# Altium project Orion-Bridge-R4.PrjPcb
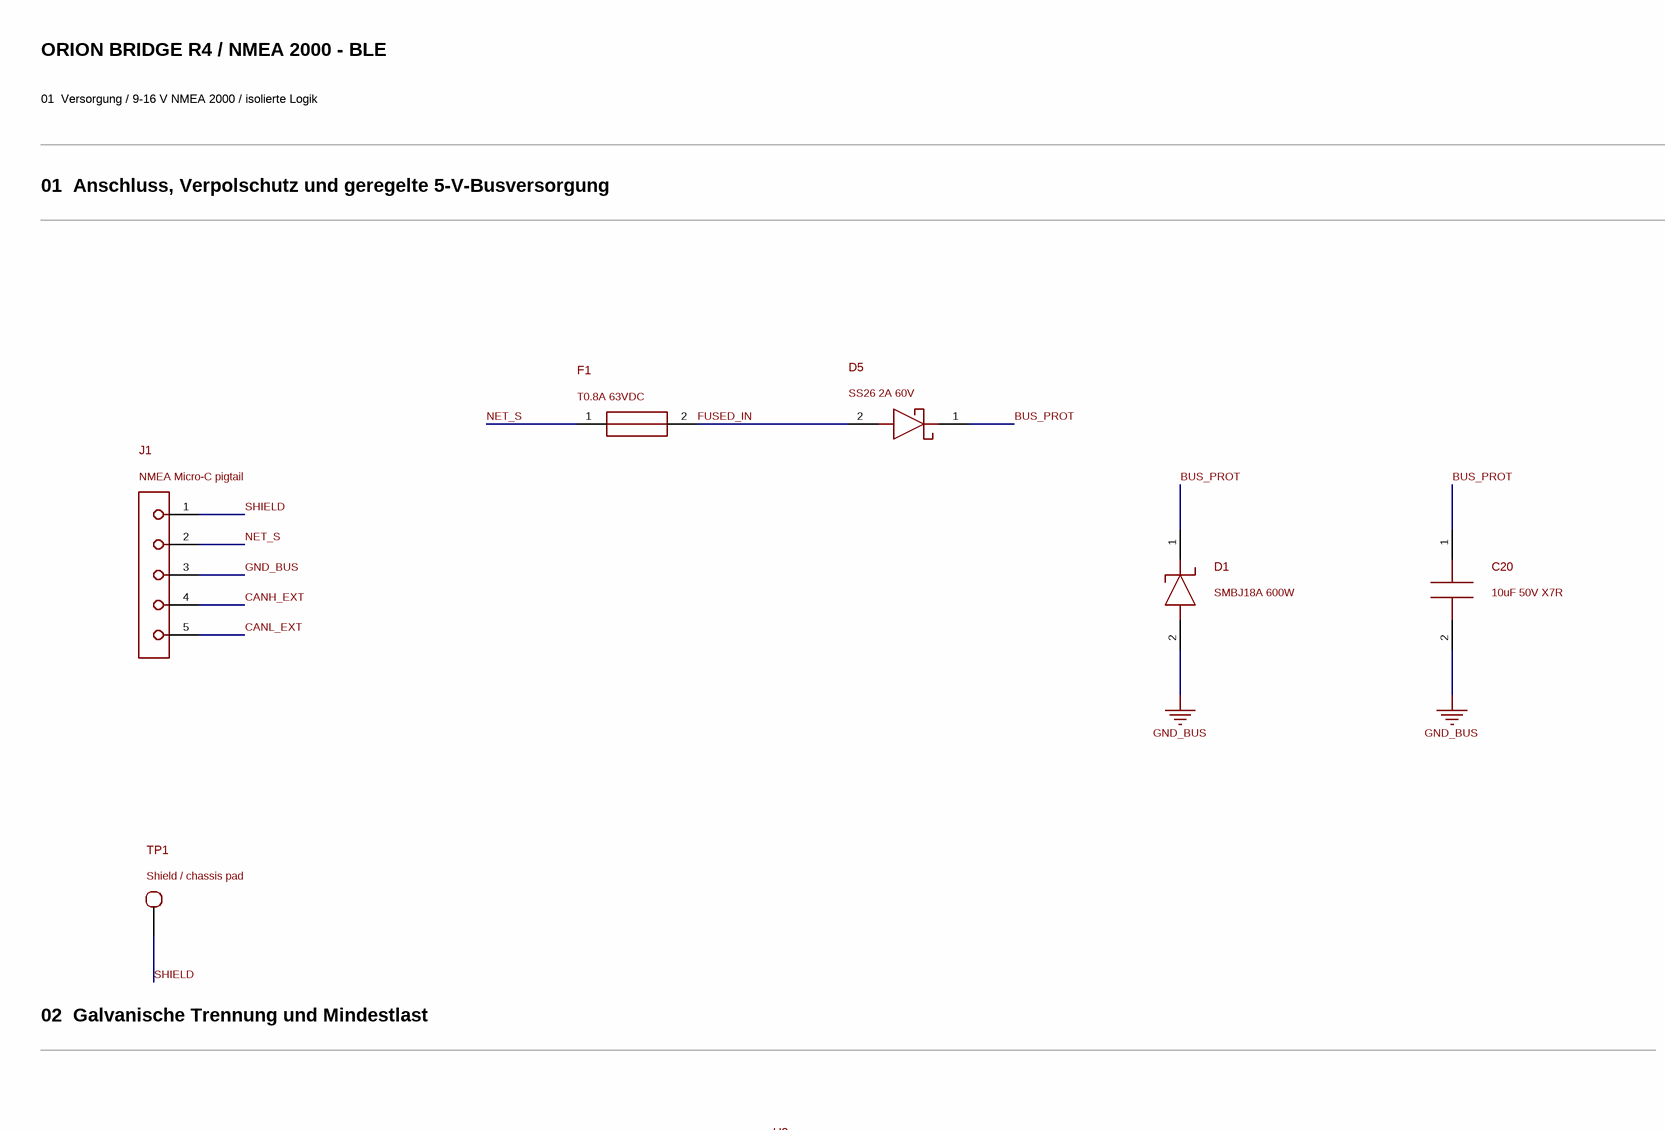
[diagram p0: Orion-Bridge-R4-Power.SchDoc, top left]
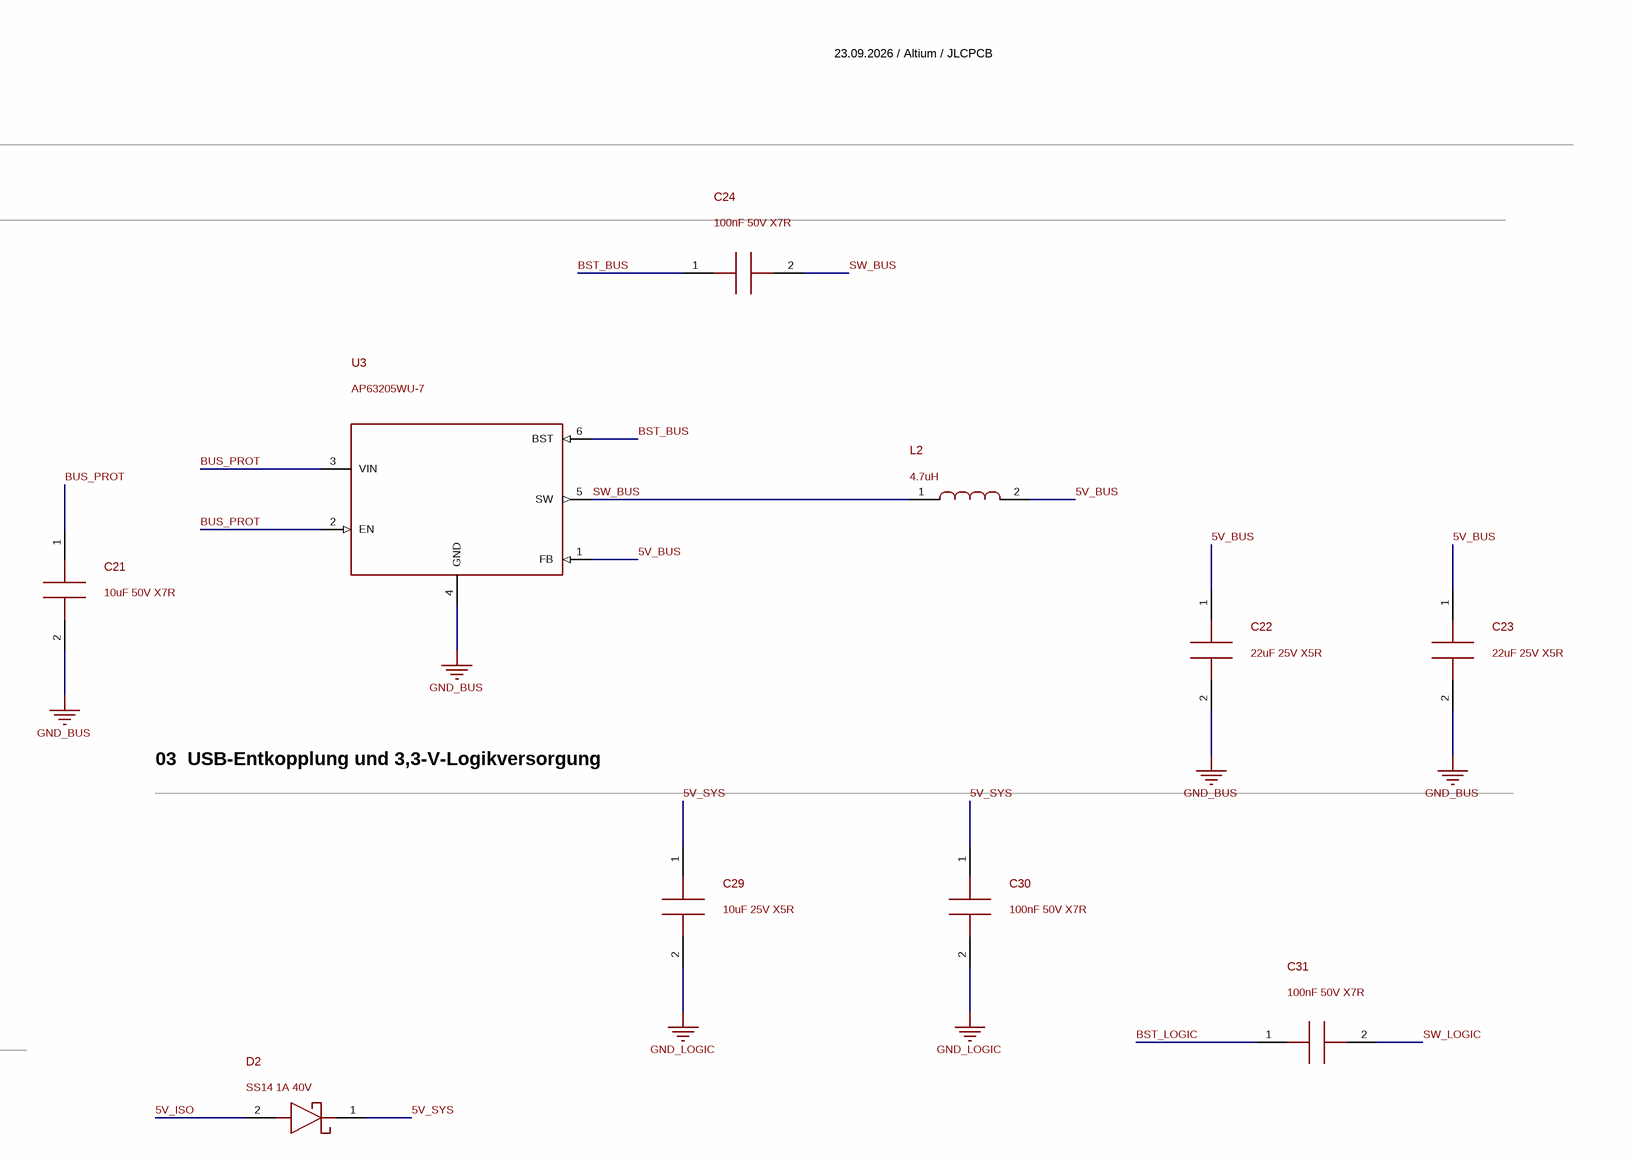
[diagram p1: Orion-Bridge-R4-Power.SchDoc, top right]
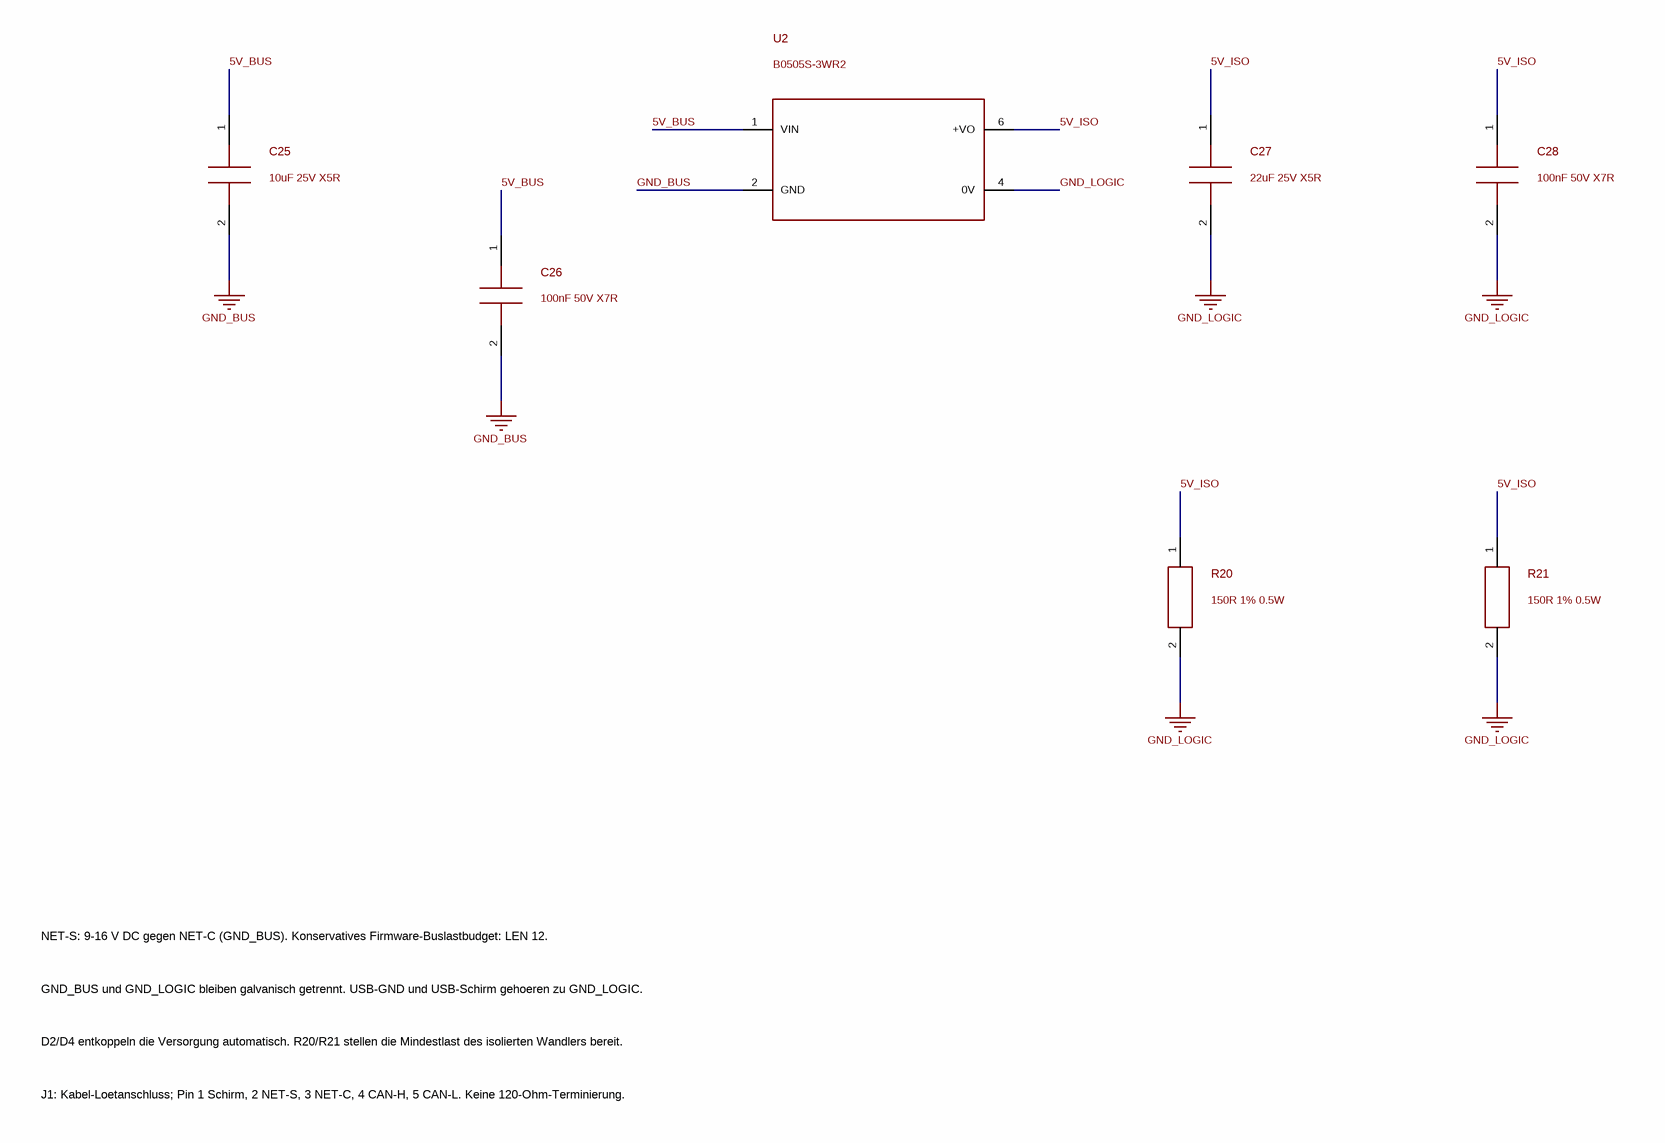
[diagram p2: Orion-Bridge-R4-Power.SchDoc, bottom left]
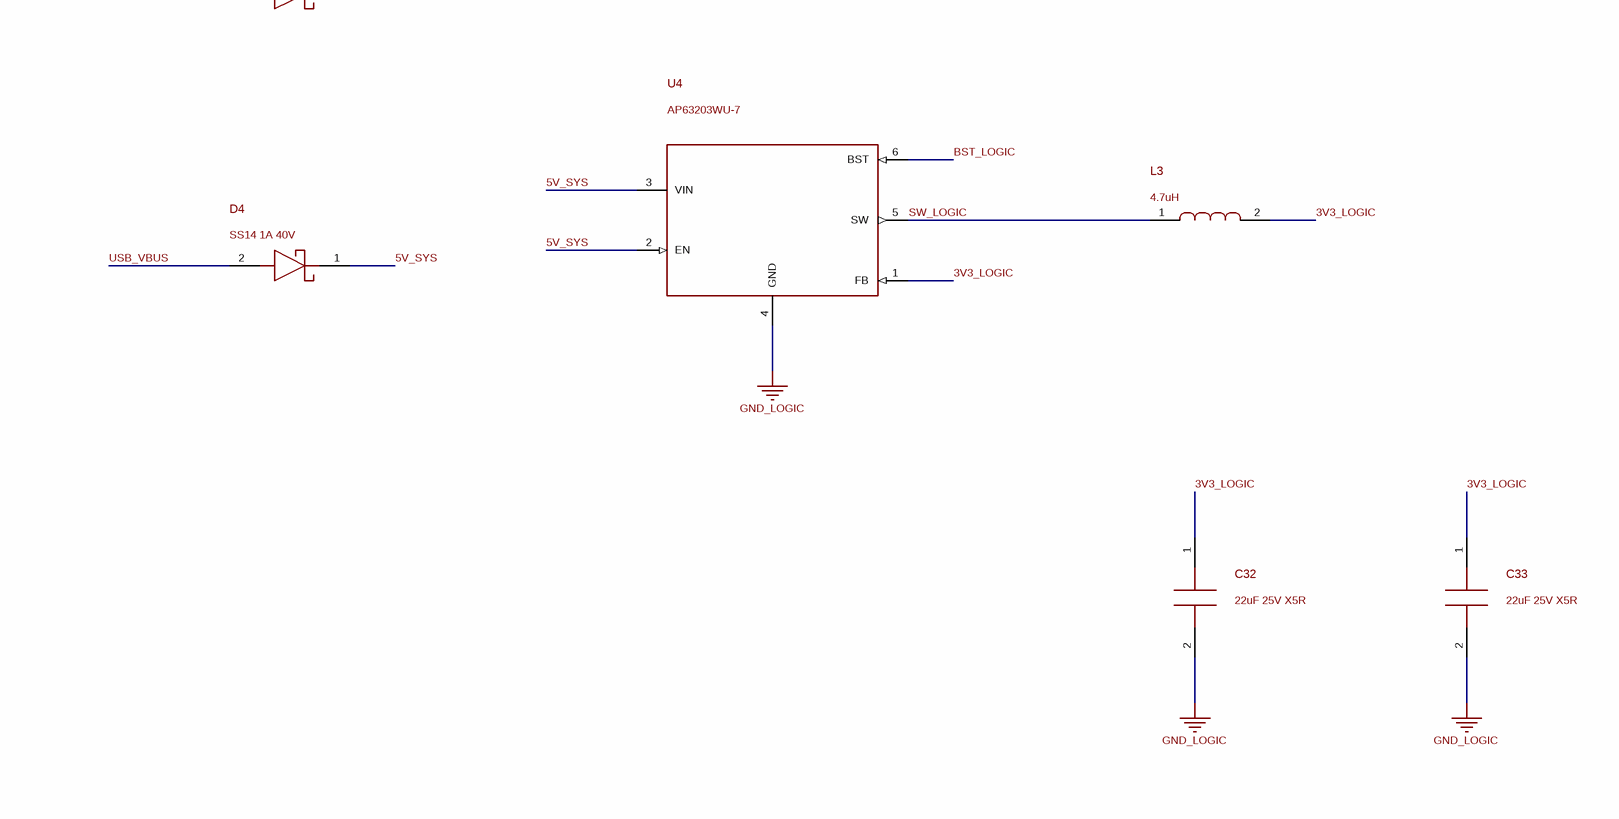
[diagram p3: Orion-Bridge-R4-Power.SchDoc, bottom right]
2 sheets, 52 parts. Net scope: global (net labels, ports and power ports of the same name join across sheets).
Board file: Orion-Bridge-R4.PcbDoc
Sheets:
  Orion-Bridge-R4-Power.SchDoc
  Orion-Bridge-R4-Logic.SchDoc

## Sheet Orion-Bridge-R4-Power.SchDoc
size A2

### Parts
C20  10uF 50V X7R  [C1210]
C21  10uF 50V X7R  [C1210]
C22  22uF 25V X5R  [C1206]
C23  22uF 25V X5R  [C1206]
C24  100nF 50V X7R  [C0603]
C25  10uF 25V X5R  [C0805]
C26  100nF 50V X7R  [C0603]
C27  22uF 25V X5R  [C1206]
C28  100nF 50V X7R  [C0603]
C29  10uF 25V X5R  [C0805]
C30  100nF 50V X7R  [C0603]
C31  100nF 50V X7R  [C0603]
C32  22uF 25V X5R  [C1206]
C33  22uF 25V X5R  [C1206]
D1  SMBJ18A 600W  [SMB]
D2  SS14 1A 40V  [SMA]
D4  SS14 1A 40V  [SMA]
D5  SS26 2A 60V  [SMA]
F1  T0.8A 63VDC  [BOURNS_SF1206S]
J1  NMEA Micro-C pigtail  [PIGTAIL_5_P3_D1P3]
L2  4.7uH  [SUNLORD_SWPA4030]
L3  4.7uH  [SUNLORD_SWPA4030]
R20  150R 1% 0.5W  [R1206]
R21  150R 1% 0.5W  [R1206]
TP1  Shield / chassis pad  [TESTPOINT_2MM]
U2  B0505S-3WR2  [EVISUN_B0505S_3WR2]
U3  AP63205WU-7  [TSOT26_DIODES]
U4  AP63203WU-7  [TSOT26_DIODES]

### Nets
GND_BUS: C20.2 C21.2 C22.2 C23.2 C25.2 C26.2 D1.2(A) J1.3(NET-C) U2.2(GND) U3.4(GND)
GND_LOGIC: C27.2 C28.2 C29.2 C30.2 C32.2 C33.2 R20.2 R21.2 U2.4(0V) U4.4(GND)
3V3_LOGIC: C32.1 C33.1 L3.2 U4.1(FB)
5V_BUS: C22.1 C23.1 C25.1 C26.1 L2.2 U2.1(VIN) U3.1(FB)
5V_ISO: C27.1 C28.1 D2.2(A) R20.1 R21.1 U2.6(+VO)
5V_SYS: C29.1 C30.1 D2.1(K) D4.1(K) U4.2(EN) U4.3(VIN)
BST_BUS: C24.1 U3.6(BST)
BST_LOGIC: C31.1 U4.6(BST)
BUS_PROT: C20.1 C21.1 D1.1(K) D5.1(K) U3.2(EN) U3.3(VIN)
CANH_EXT: J1.4(CAN-H)
CANL_EXT: J1.5(CAN-L)
FUSED_IN: D5.2(A) F1.2
NET_S: F1.1 J1.2(NET-S)
SHIELD: J1.1(SHIELD) TP1.1(SHIELD)
SW_BUS: C24.2 L2.1 U3.5(SW)
SW_LOGIC: C31.2 L3.1 U4.5(SW)
USB_VBUS: D4.2(A)

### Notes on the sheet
- ORION BRIDGE R4 / NMEA 2000 - BLE
- 23.09.2026 / Altium / JLCPCB
- 01  Versorgung / 9-16 V NMEA 2000 / isolierte Logik
- 01  Anschluss, Verpolschutz und geregelte 5-V-Busversorgung
- 03  USB-Entkopplung und 3,3-V-Logikversorgung
- 02  Galvanische Trennung und Mindestlast
- NET-S: 9-16 V DC gegen NET-C (GND_BUS). Konservatives Firmware-Buslastbudget: LEN 12.
- GND_BUS und GND_LOGIC bleiben galvanisch getrennt. USB-GND und USB-Schirm gehoeren zu GND_LOGIC.
- D2/D4 entkoppeln die Versorgung automatisch. R20/R21 stellen die Mindestlast des isolierten Wandlers bereit.
- J1: Kabel-Loetanschluss; Pin 1 Schirm, 2 NET-S, 3 NET-C, 4 CAN-H, 5 CAN-L. Keine 120-Ohm-Terminierung.

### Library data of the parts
C20 = R4_C20_10uF: Manufacturer: Samsung Electro-Mechanics; MPN: CL32B106KBJNNNE; ReviewStatus: R4 reviewed package; see source and assembly audit
C21 = R4_C21_10uF: Manufacturer: Samsung Electro-Mechanics; MPN: CL32B106KBJNNNE; ReviewStatus: R4 reviewed package; see source and assembly audit
C22 = R4_C22_22uF: Manufacturer: Samsung Electro-Mechanics; MPN: CL31A226KAHNNNE; ReviewStatus: R4 reviewed package; see source and assembly audit
C23 = R4_C23_22uF: Manufacturer: Samsung Electro-Mechanics; MPN: CL31A226KAHNNNE; ReviewStatus: R4 reviewed package; see source and assembly audit
C24 = R4_C24_100nF: Manufacturer: YAGEO; MPN: CC0603KRX7R9BB104; ReviewStatus: R4 reviewed package; see source and assembly audit
C25 = R4_C25_10uF: Manufacturer: Samsung Electro-Mechanics; MPN: CL21A106KAYNNNE; ReviewStatus: R4 reviewed package; see source and assembly audit
C26 = R4_C26_100nF: Manufacturer: YAGEO; MPN: CC0603KRX7R9BB104; ReviewStatus: R4 reviewed package; see source and assembly audit
C27 = R4_C27_22uF: Manufacturer: Samsung Electro-Mechanics; MPN: CL31A226KAHNNNE; ReviewStatus: R4 reviewed package; see source and assembly audit
C28 = R4_C28_100nF: Manufacturer: YAGEO; MPN: CC0603KRX7R9BB104; ReviewStatus: R4 reviewed package; see source and assembly audit
C29 = R4_C29_10uF: Manufacturer: Samsung Electro-Mechanics; MPN: CL21A106KAYNNNE; ReviewStatus: R4 reviewed package; see source and assembly audit
C30 = R4_C30_100nF: Manufacturer: YAGEO; MPN: CC0603KRX7R9BB104; ReviewStatus: R4 reviewed package; see source and assembly audit
C31 = R4_C31_100nF: Manufacturer: YAGEO; MPN: CC0603KRX7R9BB104; ReviewStatus: R4 reviewed package; see source and assembly audit
C32 = R4_C32_22uF: Manufacturer: Samsung Electro-Mechanics; MPN: CL31A226KAHNNNE; ReviewStatus: R4 reviewed package; see source and assembly audit
C33 = R4_C33_22uF: Manufacturer: Samsung Electro-Mechanics; MPN: CL31A226KAHNNNE; ReviewStatus: R4 reviewed package; see source and assembly audit
D1 = R4_D1_SMBJ18A: Manufacturer: BORN; ReviewStatus: R4 reviewed package; see source and assembly audit
D2 = R4_D2_SS14: Manufacturer: MDD(Microdiode Semiconductor); ReviewStatus: R4 reviewed package; see source and assembly audit
D4 = R4_D4_SS14: Manufacturer: MDD(Microdiode Semiconductor); ReviewStatus: R4 reviewed package; see source and assembly audit
D5 = R4_D5_SS26: Manufacturer: MDD(Microdiode Semiconductor); ReviewStatus: R4 reviewed package; see source and assembly audit
F1 = R4_F1_T0.8A: 0.8 A slow-blow SMD ceramic fuse, 63 VDC, 50 A interrupt rating; Manufacturer: BOURNS; MPN: SF-1206S080-2; ReviewStatus: R4 reviewed package; see source and assembly audit
J1 = R4_J1_NMEA: Five direct wire-solder pads for a separately selected Micro-C cable; this is a PCB interface, not an invented connector MPN or face view; ReviewStatus: R4 reviewed package; see source and assembly audit
L2 = R4_L2_4.7uH: Manufacturer: Sunlord; MPN: SWPA4030S4R7MT; ReviewStatus: R4 reviewed package; see source and assembly audit
L3 = R4_L3_4.7uH: Manufacturer: Sunlord; MPN: SWPA4030S4R7MT; ReviewStatus: R4 reviewed package; see source and assembly audit
R20 = R4_R20_150R: Manufacturer: SEI(Stackpole Elec); MPN: RNCP1206FTD150R; ReviewStatus: R4 reviewed package; see source and assembly audit
R21 = R4_R21_150R: Manufacturer: SEI(Stackpole Elec); MPN: RNCP1206FTD150R; ReviewStatus: R4 reviewed package; see source and assembly audit
TP1 = R4_TP1_Shield: Shield / chassis pad - generic specification; manufacturer/MPN not selected; ReviewStatus: R4 reviewed package; see source and assembly audit
U2 = R4_U2_B0505S_3WR2: Manufacturer: EVISUN; ReviewStatus: R4 reviewed package; see source and assembly audit
U3 = R4_U3_AP63205WU_7: Manufacturer: Diodes Incorporated; ReviewStatus: R4 reviewed package; see source and assembly audit
U4 = R4_U4_AP63203WU_7: Manufacturer: Diodes Incorporated; ReviewStatus: R4 reviewed package; see source and assembly audit

## Sheet Orion-Bridge-R4-Logic.SchDoc
size A2
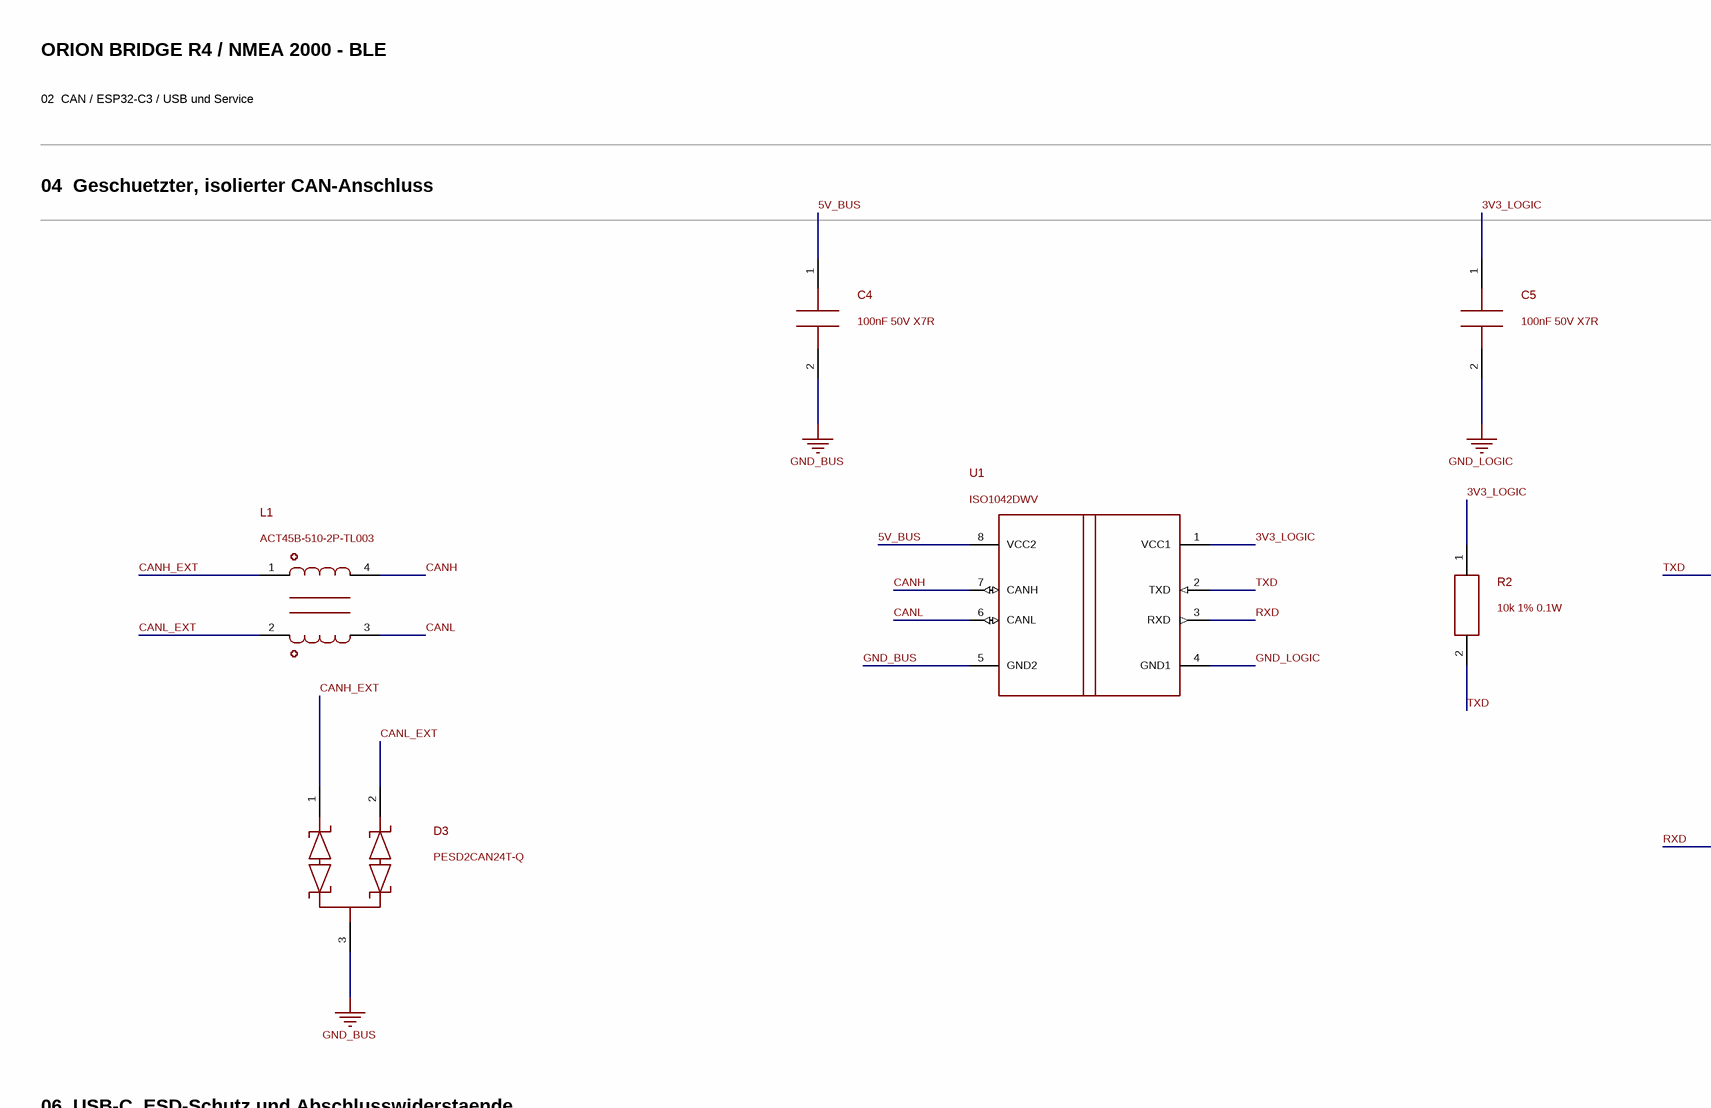
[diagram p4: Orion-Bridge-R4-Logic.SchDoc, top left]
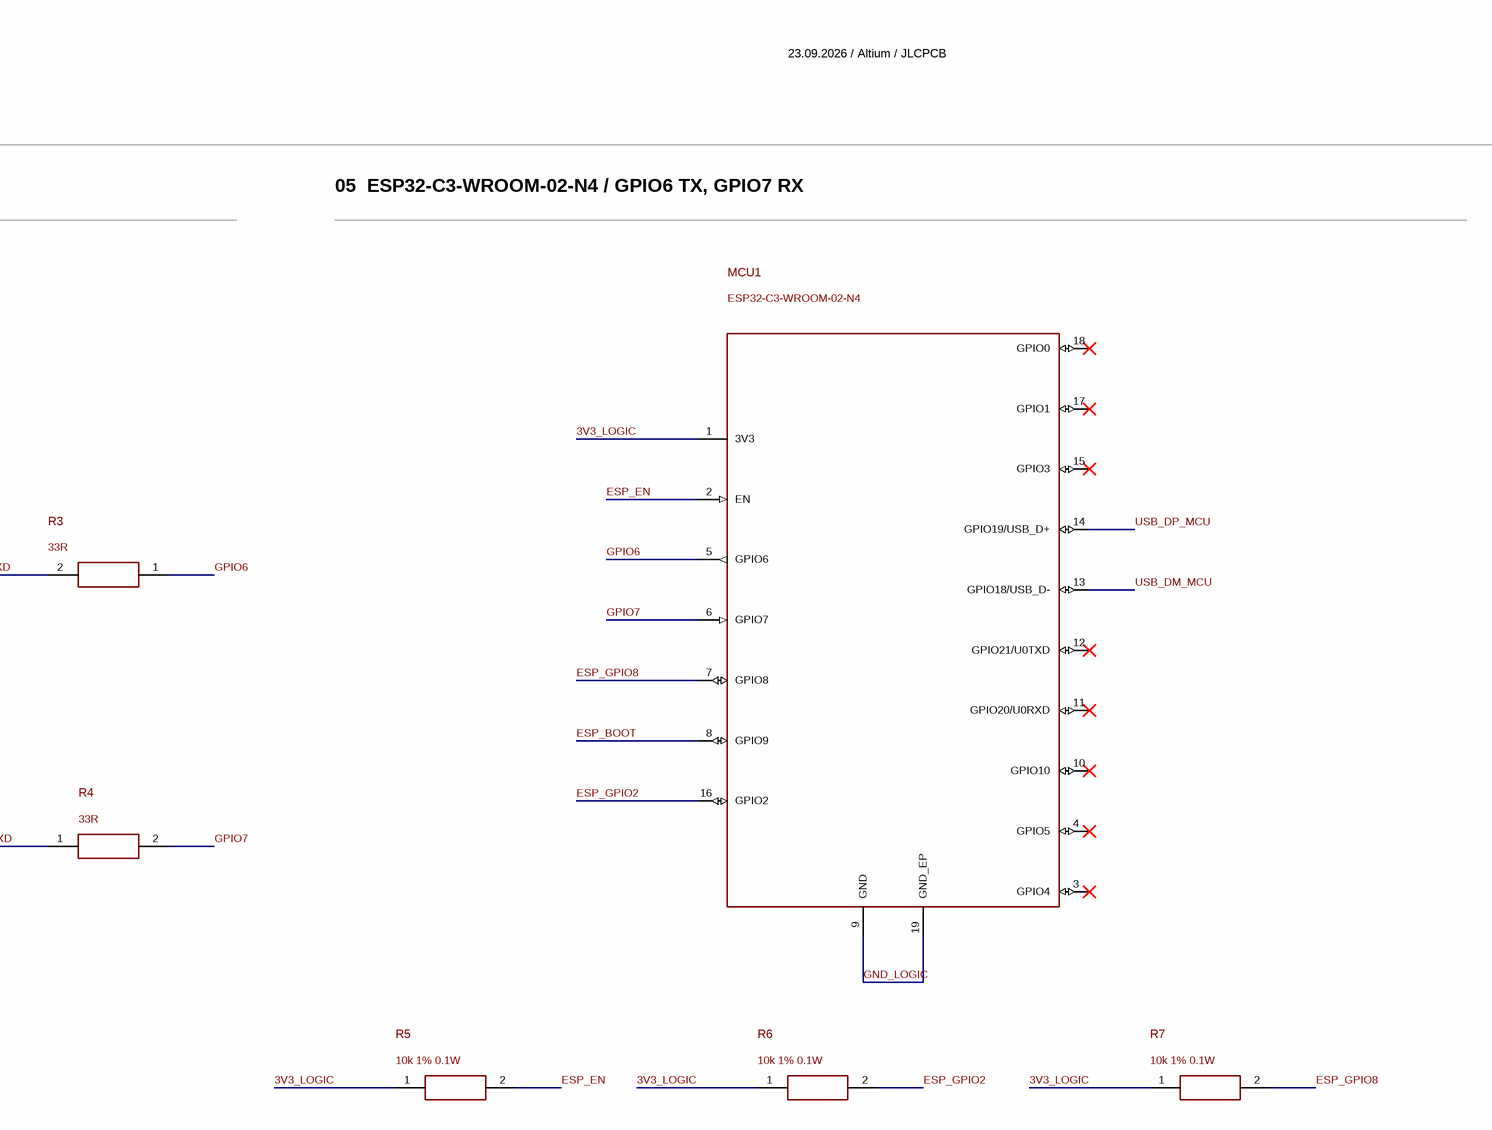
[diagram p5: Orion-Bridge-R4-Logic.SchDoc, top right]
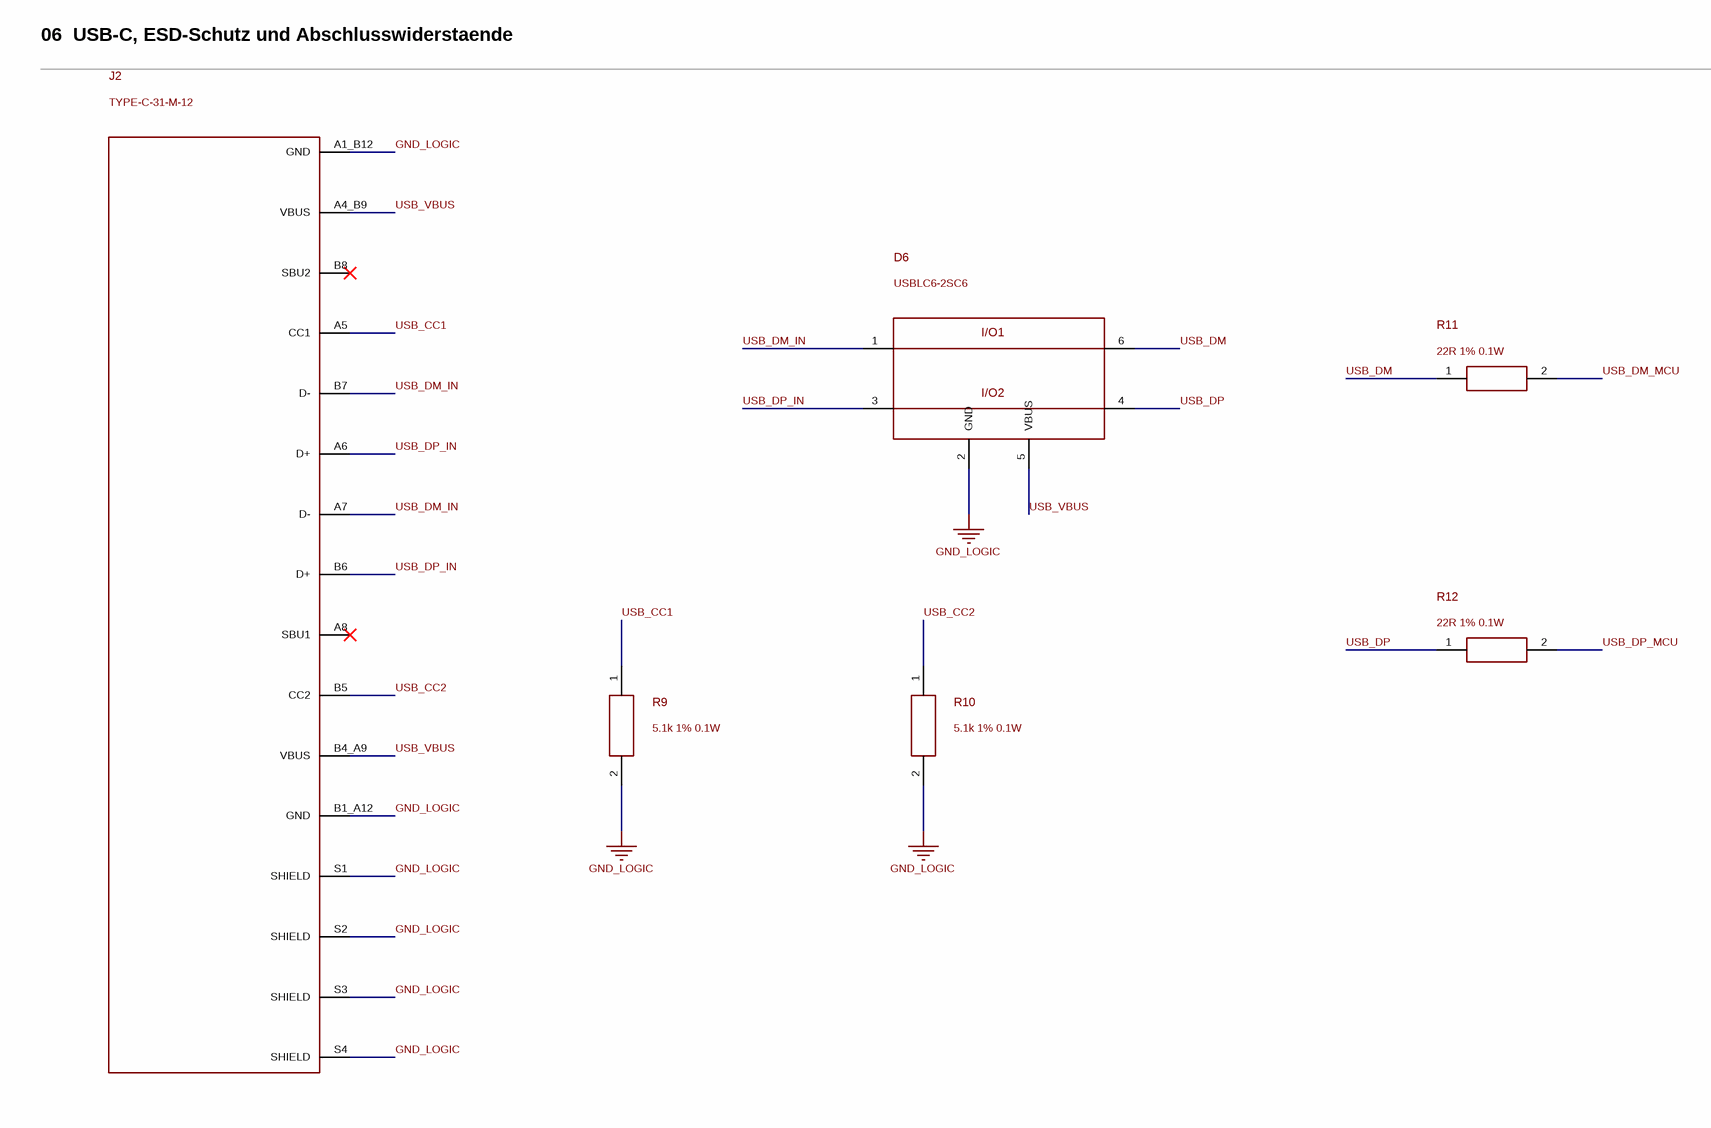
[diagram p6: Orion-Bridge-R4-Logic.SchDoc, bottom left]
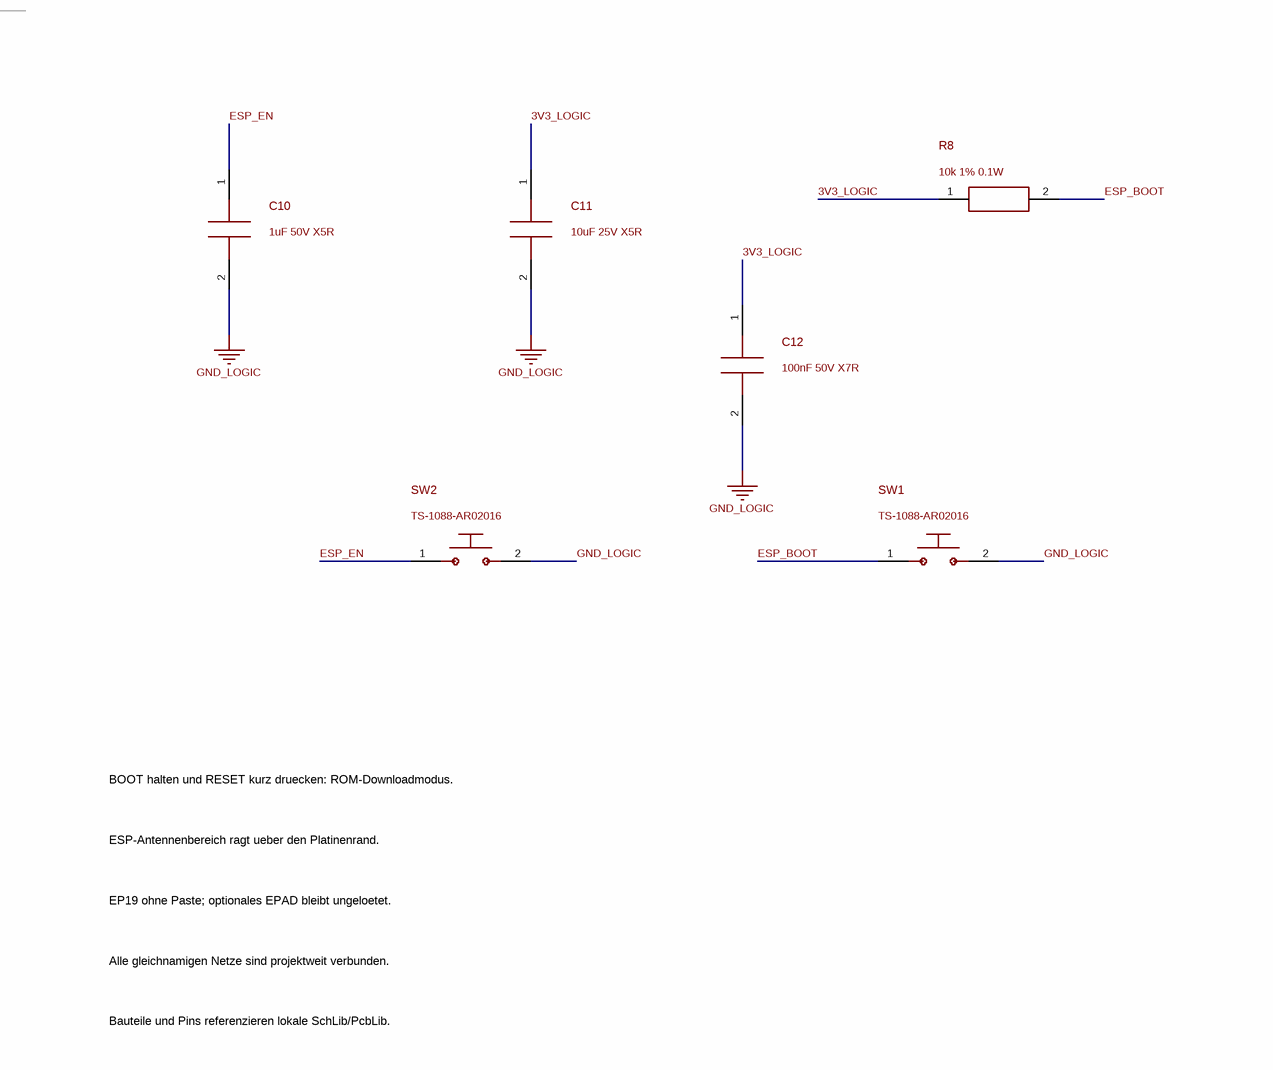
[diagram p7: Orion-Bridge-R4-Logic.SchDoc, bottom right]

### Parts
C4  100nF 50V X7R  [C0603]
C5  100nF 50V X7R  [C0603]
C10  1uF 50V X5R  [C0603]
C11  10uF 25V X5R  [C0805]
C12  100nF 50V X7R  [C0603]
D3  PESD2CAN24T-Q  [SOT23_NEXPERIA_REFLOW]
D6  USBLC6-2SC6  [SOT23_6_ST_USBLC6]
J2  TYPE-C-31-M-12  [USB_C_HRO_TYPE_C_31_M_12_2020]
L1  ACT45B-510-2P-TL003  [ACT45B]
MCU1  ESP32-C3-WROOM-02-N4  [ESP32_C3_WROOM_02]
R2  10k 1% 0.1W  [R0603]
R3  33R  [R0603]
R4  33R  [R0603]
R5  10k 1% 0.1W  [R0603]
R6  10k 1% 0.1W  [R0603]
R7  10k 1% 0.1W  [R0603]
R8  10k 1% 0.1W  [R0603]
R9  5.1k 1% 0.1W  [R0603]
R10  5.1k 1% 0.1W  [R0603]
R11  22R 1% 0.1W  [R0603]
R12  22R 1% 0.1W  [R0603]
SW1  TS-1088-AR02016  [SW_XUNPU_TS1088_AR]
SW2  TS-1088-AR02016  [SW_XUNPU_TS1088_AR]
U1  ISO1042DWV  [SOIC8_DWV]

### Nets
GND_BUS: C4.2 D3.3(CC) U1.5(GND2)
GND_LOGIC: C5.2 C10.2 C11.2 C12.2 D6.2(GND) J2.A1_B12(GND) J2.B1_A12(GND) J2.S1(SHIELD) J2.S2(SHIELD) J2.S3(SHIELD) J2.S4(SHIELD) MCU1.9(GND) MCU1.19(GND_EP) R9.2 R10.2 SW1.2(B) SW2.2(B) U1.4(GND1)
3V3_LOGIC: C5.1 C11.1 C12.1 MCU1.1(3V3) R2.1 R5.1 R6.1 R7.1 R8.1 U1.1(VCC1)
5V_BUS: C4.1 U1.8(VCC2)
CANH: L1.4(H_IC) U1.7(CANH)
CANH_EXT: D3.1(K1) L1.1(H_EXT)
CANL: L1.3(L_IC) U1.6(CANL)
CANL_EXT: D3.2(K2) L1.2(L_EXT)
ESP_BOOT: MCU1.8(GPIO9) R8.2 SW1.1(A)
ESP_EN: C10.1 MCU1.2(EN) R5.2 SW2.1(A)
ESP_GPIO2: MCU1.16(GPIO2) R6.2
ESP_GPIO8: MCU1.7(GPIO8) R7.2
GPIO6: MCU1.5(GPIO6) R3.1
GPIO7: MCU1.6(GPIO7) R4.2
RXD: R4.1 U1.3(RXD)
TXD: R2.2 R3.2 U1.2(TXD)
USB_CC1: J2.A5(CC1) R9.1
USB_CC2: J2.B5(CC2) R10.1
USB_DM: D6.6(IO1) R11.1
USB_DM_IN: D6.1(IO1) J2.A7(D-) J2.B7(D-)
USB_DM_MCU: MCU1.13(GPIO18/USB_D-) R11.2
USB_DP: D6.4(IO2) R12.1
USB_DP_IN: D6.3(IO2) J2.A6(D+) J2.B6(D+)
USB_DP_MCU: MCU1.14(GPIO19/USB_D+) R12.2
USB_VBUS: D6.5(VBUS) J2.A4_B9(VBUS) J2.B4_A9(VBUS)

Not connected (* = marked no-connect by the designer): J2 A8(SBU1)* B8(SBU2)*; MCU1 3(GPIO4)* 4(GPIO5)* 10(GPIO10)* 11(GPIO20/U0RXD)* 12(GPIO21/U0TXD)* 15(GPIO3)* 17(GPIO1)* 18(GPIO0)*

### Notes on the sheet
- ORION BRIDGE R4 / NMEA 2000 - BLE
- 23.09.2026 / Altium / JLCPCB
- 02  CAN / ESP32-C3 / USB und Service
- 04  Geschuetzter, isolierter CAN-Anschluss
- 05  ESP32-C3-WROOM-02-N4 / GPIO6 TX, GPIO7 RX
- 06  USB-C, ESD-Schutz und Abschlusswiderstaende
- BOOT halten und RESET kurz druecken: ROM-Downloadmodus.
- ESP-Antennenbereich ragt ueber den Platinenrand.
- EP19 ohne Paste; optionales EPAD bleibt ungeloetet.
- Alle gleichnamigen Netze sind projektweit verbunden.
- Bauteile und Pins referenzieren lokale SchLib/PcbLib.

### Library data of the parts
C4 = R4_C4_100nF: 100nF 16V X7R - generic specification; manufacturer/MPN not selected; Manufacturer: YAGEO; MPN: CC0603KRX7R9BB104; ReviewStatus: R4 reviewed package; see source and assembly audit
C5 = R4_C5_100nF: 100nF 16V X7R - generic specification; manufacturer/MPN not selected; Manufacturer: YAGEO; MPN: CC0603KRX7R9BB104; ReviewStatus: R4 reviewed package; see source and assembly audit
C10 = R4_C10_1uF: Manufacturer: Samsung Electro-Mechanics; MPN: CL10A105KB8NNNC; ReviewStatus: R4 reviewed package; see source and assembly audit
C11 = R4_C11_10uF: Manufacturer: Samsung Electro-Mechanics; MPN: CL21A106KAYNNNE; ReviewStatus: R4 reviewed package; see source and assembly audit
C12 = R4_C12_100nF: Manufacturer: YAGEO; MPN: CC0603KRX7R9BB104; ReviewStatus: R4 reviewed package; see source and assembly audit
D3 = R4_D3_PESD2CAN24T_Q: Manufacturer: Nexperia; MPN: PESD2CAN24T-QR; ReviewStatus: R4 reviewed package; see source and assembly audit
D6 = R4_D6_USBLC6_2SC6: Manufacturer: STMicroelectronics; ReviewStatus: R4 reviewed package; see source and assembly audit
J2 = R4_J2_TYPE_C_31_M_12: Manufacturer: Korean Hroparts Elec; ReviewStatus: R4 reviewed package; see source and assembly audit
L1 = R4_L1_ACT45B_510_2P_TL003: Manufacturer: TDK; ReviewStatus: R4 reviewed package; see source and assembly audit
MCU1 = R4_MCU1_ESP32_C3_WROOM_02_N4: Manufacturer: Espressif Systems; ReviewStatus: R4 reviewed package; see source and assembly audit
R2 = R4_R2_10k: 10k - generic specification; manufacturer/MPN not selected; Manufacturer: UNI-ROYAL(Uniroyal Elec); MPN: 0603WAF1002T5E; ReviewStatus: R4 reviewed package; see source and assembly audit
R3 = R4_R3_33R: 33R - generic specification; manufacturer/MPN not selected; Manufacturer: UNI-ROYAL(Uniroyal Elec); MPN: 0603WAF330JT5E; Role: R_TX; ReviewStatus: R4 reviewed package; see source and assembly audit
R4 = R4_R4_33R: 33R - generic specification; manufacturer/MPN not selected; Manufacturer: UNI-ROYAL(Uniroyal Elec); MPN: 0603WAF330JT5E; Role: R_RX; ReviewStatus: R4 reviewed package; see source and assembly audit
R5 = R4_R5_10k: Manufacturer: UNI-ROYAL(Uniroyal Elec); MPN: 0603WAF1002T5E; ReviewStatus: R4 reviewed package; see source and assembly audit
R6 = R4_R6_10k: Manufacturer: UNI-ROYAL(Uniroyal Elec); MPN: 0603WAF1002T5E; ReviewStatus: R4 reviewed package; see source and assembly audit
R7 = R4_R7_10k: Manufacturer: UNI-ROYAL(Uniroyal Elec); MPN: 0603WAF1002T5E; ReviewStatus: R4 reviewed package; see source and assembly audit
R8 = R4_R8_10k: Manufacturer: UNI-ROYAL(Uniroyal Elec); MPN: 0603WAF1002T5E; ReviewStatus: R4 reviewed package; see source and assembly audit
R9 = R4_R9_5.1k: Manufacturer: UNI-ROYAL(Uniroyal Elec); MPN: 0603WAF5101T5E; ReviewStatus: R4 reviewed package; see source and assembly audit
R10 = R4_R10_5.1k: Manufacturer: UNI-ROYAL(Uniroyal Elec); MPN: 0603WAF5101T5E; ReviewStatus: R4 reviewed package; see source and assembly audit
R11 = R4_R11_22R: Manufacturer: UNI-ROYAL(Uniroyal Elec); MPN: 0603WAF220JT5E; ReviewStatus: R4 reviewed package; see source and assembly audit
R12 = R4_R12_22R: Manufacturer: UNI-ROYAL(Uniroyal Elec); MPN: 0603WAF220JT5E; ReviewStatus: R4 reviewed package; see source and assembly audit
SW1 = R4_SW1_TS_1088_AR02016: Manufacturer: XUNPU; ReviewStatus: R4 reviewed package; see source and assembly audit
SW2 = R4_SW2_TS_1088_AR02016: Manufacturer: XUNPU; ReviewStatus: R4 reviewed package; see source and assembly audit
U1 = R4_U1_ISO1042DWV: Manufacturer: Texas Instruments; MPN: ISO1042DWVR; ReviewStatus: R4 reviewed package; see source and assembly audit

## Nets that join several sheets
GND_BUS: Orion-Bridge-R4-Power (10 pins), Orion-Bridge-R4-Logic (C4.2 D3.3 U1.5)
GND_LOGIC: Orion-Bridge-R4-Power (10 pins), Orion-Bridge-R4-Logic (18 pins)
3V3_LOGIC: Orion-Bridge-R4-Power (C32.1 C33.1 L3.2 U4.1), Orion-Bridge-R4-Logic (10 pins)
5V_BUS: Orion-Bridge-R4-Power (7 pins), Orion-Bridge-R4-Logic (C4.1 U1.8)
CANH_EXT: Orion-Bridge-R4-Power (J1.4), Orion-Bridge-R4-Logic (D3.1 L1.1)
CANL_EXT: Orion-Bridge-R4-Power (J1.5), Orion-Bridge-R4-Logic (D3.2 L1.2)
USB_VBUS: Orion-Bridge-R4-Power (D4.2), Orion-Bridge-R4-Logic (D6.5 J2.A4_B9 J2.B4_A9)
